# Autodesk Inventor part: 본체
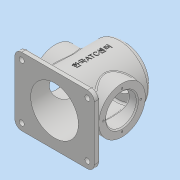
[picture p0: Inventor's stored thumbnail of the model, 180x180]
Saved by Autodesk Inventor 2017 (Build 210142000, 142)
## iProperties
Part Number: 본체
Material: 일반
Document SubType Name: Modeling
Designer: MRC
Density: 1 g/cm^3
Appearance: 기본값
Author: MRC
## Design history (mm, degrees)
sketch "스케치1"
  geometry: C1 r 50 at (0, 0); 1 further point
  constraints: 1 centre point, 1 coincident
  dimensions: "d0" = 100 diameter of C1
extrude "돌출1" new body sketch "스케치1" stored distance "d1" = 120; taper "d2" = 0 deg
sketch "스케치2"
  geometry: C1 r 41 at (0, 0); 1 further point
  constraints: 1 centre point, 1 coincident
  dimensions: "d3" = 82 diameter of C1
extrude "돌출2" join sketch "스케치2" distance "d4" = 5; taper "d5" = 0 deg
sketch "스케치3"
  geometry: L1 (70, -60)-(-70, -60); L2 (-70, -60)-(-70, 60); L3 (-70, 60)-(70, 60); L4 (70, 60)-(70, -60); L5 (70, -60)-(-70, 60); L6 (-70, -60)-(70, 60); 1 further point
  constraints: 12 end point, 2 midpoint, 2 parallel, 1 horizontal, 1 perpendicular
  dimensions: "d6" = 140 distance of L2.end L3.end; "d7" = 120 distance of L1.end L2.end
extrude "돌출3" join sketch "스케치3" distance "d8" = 10; taper "d9" = 0 deg
node "작업 평면1"
sketch "스케치4"
  geometry: C1 r 41 at (0, 0); 1 further point
  constraints: 1 centre point, 1 coincident
  dimensions: "d11" = 82 diameter of C1
extrude "돌출4" join sketch "스케치4" stored distance "d12" = 10; taper "d13" = 0 deg
sketch "스케치5"
  geometry: C1 r 42 at (0, 0); 1 further point
  constraints: 1 centre point, 1 coincident
  dimensions: "d14" = 84 diameter of C1
extrude "돌출5" cut sketch "스케치5" distance "d15" = 112; taper "d16" = 0 deg
sketch "스케치6"
  geometry: C1 r 27 at (0, 0); 1 further point
  constraints: 1 centre point, 1 coincident
  dimensions: "d17" = 54 diameter of C1
extrude "돌출6" cut sketch "스케치6" distance "d18" = 13; taper "d19" = 0 deg
sketch "스케치7"
  geometry: 2 further points
  constraints: 1 horizontal alignment
  dimensions: "d20" = 33 distance of point (0, 0) point (-33, 0)
hole "구멍1" sketch "스케치7" at (-33, 0) diameter "d21" = 3.242; stored, may be unused: countersink angle "d25" = 90 deg, drill point angle "d27" = 118 deg; dims "d22" = 8, "d23" = 4, "d24" = 2, "d26" = 10
sketch "스케치8"
  geometry: 2 further points
  constraints: 1 vertical alignment
  dimensions: "d28" = 33 distance of point (0, 0) point (0, 33)
hole "구멍2" sketch "스케치8" at (0, 33) diameter "d29" = 3.242; stored, may be unused: countersink angle "d33" = 90 deg, drill point angle "d35" = 118 deg; dims "d30" = 8, "d31" = 4, "d32" = 2, "d34" = 10
sketch "스케치9"
  geometry: C1 r 27 at (0, 0); 1 further point
  constraints: 1 centre point, 1 coincident
  dimensions: "d36" = 54 diameter of C1
extrude "돌출7" cut sketch "스케치9" stored distance "d37" = 13; taper "d38" = 0 deg
chamfer "모따기1" distance "d45" = 2; stored, may be unused: second distance "d46" = 2, angle "d47" = 45 deg
fillet "모깎기1" dims "d48" = 12
fillet "모깎기2" dims "d49" = 3
fillet "모깎기3" dims "d50" = 6
fillet "모깎기4" dims "d51" = 3
node "작업 평면2"
sketch "스케치10"
  geometry: L1 (-58, -60)-(58, -60) reference; 2 further points
  constraints: 1 vertical alignment, 1 other
  dimensions: "d53" = 66 distance from line of point (0, 6) L1
feature "엠보싱1" sketch "스케치10" dims "d11" = 82, "d54" = 0.5, "d55" = 0
sketch "스케치11"
  geometry: C1 r 4.5 at (-58, 48); A1 r 12 centre (-58, 48) between (-58, 60) and (-70, 48) reference; 1 further point
  constraints: 1 centre point, 1 concentric
  dimensions: "d56" = 9 diameter of C1
extrude "돌출8" cut sketch "스케치11" stored distance "d57" = 13; taper "d58" = 0 deg
node "솔리드1"
pattern_circular "원형 패턴1" dims angle "d40" = 360 deg
pattern_circular "원형 패턴2" dims angle "d43" = 360 deg
mirror "미러1"
mirror "미러2"
mirror "미러3"
other parameters: "d10" = 59
